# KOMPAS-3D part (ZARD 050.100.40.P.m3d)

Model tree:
1. Булева операция:1
2. Булева операция:2
3. Булева операция:3
4. Булева операция:4
5. Булева операция:5
6. Булева операция:6
7. Булева операция:7
8. Булева операция:8
9. Булева операция:9
10. Булева операция:10
11. Булева операция:11
12. Булева операция:12
13. Булева операция:13
14. Булева операция:14
15. Булева операция:15
16. Булева операция:16
17. Булева операция:17
18. Булева операция:18
19. Булева операция:19
20. Булева операция:20
21. Булева операция:21
22. Булева операция:22  (labels: C:\Program Files\ASCON\KOMPAS-3D V13\Sys\graphic.lyt)

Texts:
  ООО ИК Энерпред-Ярдос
